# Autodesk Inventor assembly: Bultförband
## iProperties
Created: 2007-05
Part Number: Bultförband
Document SubType Name: Assembly
Designer: kurs1
Manufacturer: Standard
Standards Organization: Custom
Author: kurs1
